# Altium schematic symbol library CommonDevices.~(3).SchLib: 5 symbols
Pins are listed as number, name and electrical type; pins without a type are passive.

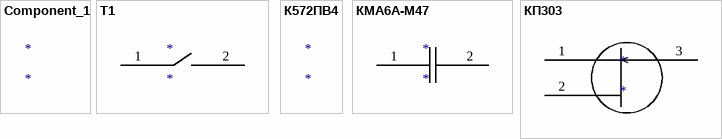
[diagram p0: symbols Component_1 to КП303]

## Component_1
designator *

## T1
designator *
pins: 1, 2

## К572ПВ4
designator *

## КМА6А-М47
designator *
pins: 1, 2

## КП303
designator *
pins: 1, 2, 3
